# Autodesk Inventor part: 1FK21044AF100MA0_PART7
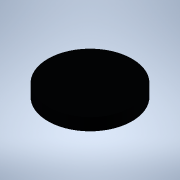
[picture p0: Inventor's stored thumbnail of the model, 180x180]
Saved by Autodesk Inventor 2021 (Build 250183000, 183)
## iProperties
Created: 2025-04
Part Number: 1FK21044AF100MA0_PART7
Material: Generic
Catalog Web Link: www.3dfindit.com
Description: -Servo synchronous motor
Document SubType Name: Modeling
Designer: psAdmin
Mass: 0.299142 g
Surface Area: 3.8585 cm^2
Volume: 0.299142 cm^3
Density: 1 g/cm^3
Appearance: PSOLRGB-38-46-56
Category: PARTsolutions
Title: 1FK21044AF100MA0_PART7
Author: Cadenas PARTsolutions
Comments: Servo synchronous motor
Sending System: PARTsolutions
Preprocessor: ST-DEVELOPER v19.3
PSOL_IDENT_0: {$CADENAS_DATA/23d-libs/siemens_ag/_cat_/ec/e4/1fk21044af100ma0.prj},213 {VTYP=3D},{NB=1FK21044AF100
PSOL_IDENT_1: MA0_PART7},{LINA=1FK21044AF100MA0_PART7},{NN=1FK21044AF100MA0_PART7},{NOPRJ=TRUE},{DATE=19.08.2025 1
PSOL_IDENT_2: 4:01:05},{GEOMDATE=30.07.2025 02:01:01},{VERSION=},{LINEID=10},{WBVAR=},{WBNUMERIC=}  {NB=1FK21044AF
PSOL_IDENT_3: 100MA0_PART7},{LINA=1FK21044AF100MA0_PART7},{KT=DUMMY},{PREVIEW=../../../_pool_/cb/72/p_d211_xx_0043
PSOL_IDENT_4: 4j.png},{DESCSHORT=SIMOTICS S-1FK2 HD, SINAMICS S210 3AC 400V-480V, 1.27 Nm, 3000 rpm},{DESCLONG=SIM
PSOL_IDENT_5: OTICS S-1FK2 HD servo motor M0=1.27 Nm; PN = 0.4 kW at nN=3000 rpm (380-480 V); PN = 0.2 kW at nN=15
PSOL_IDENT_6: 00 rpm (200-240 V); with holding brake; degree of protection IP64; cylindrical shaft D19x40mm; absol
PSOL_IDENT_7: ute encoder 22-bit + 12-bit multiturn (encoder AM22DQC); with OCC interface; plug size M17, rotatabl
PSOL_IDENT_8: e; SIMOTICS S-1FK2 servomotorfor a wide range of uses in industrial environments. SIMOTICS S‑1FK2 se
PSOL_IDENT_9: rvomotors are compact synchronous motors with a high dynamic performance that set themselves apart a
PSOL_IDENT_10: s a result of their high power density, degree of protection and overload capability. The motors are
PSOL_IDENT_11: available in two variants: as High Dynamic variant (highest dynamic performance as a result of the
PSOL_IDENT_12: low intrinsic moment of inertia for applications demanding a high dynamic performance with low moved
PSOL_IDENT_13: masses) - and as Compact variant (precise and stable closed-loop control for medium up to large mov
PSOL_IDENT_14: ed masses as a result of a medium intrinsic moment of inertia). SIMOTICSS‑1FK2 servomotors fully exp
PSOL_IDENT_15: loit their strengths in a system with the SINAMICSS210 frequency converter and simple connection usi
PSOL_IDENT_16: ng the one cable connection (OCC). Advantages include the short control and positioning times, fast
PSOL_IDENT_17: and precise correction of disturbing quantities as well as stable control with a high dynamic perfor
PSOL_IDENT_18: mance. The servo motors can be configured to address a wide range of requirements. For example with
PSOL_IDENT_19: and without holding brake, IP64 or IP65 degree of protection, singleturn or multiturn absolute encod
PSOL_IDENT_20: ers - to name just a few. Further, the servomotors are available in different shaft heights extendin
PSOL_IDENT_21: g from 20 to 100. A shaft sealing ring is available to achieve an IP65 degree of protection and for
PSOL_IDENT_22: subsequent mounting at the motor or as spare part. SIMOTICS - the optimum motor for each and every m
PSOL_IDENT_23: otion control application.},{INTNO=195125043275},{SUPPLIERALTNO=1FK2104-4AF10-0MA0},{MANUID=1FK21044
PSOL_IDENT_24: AF100MA0},{MANUNAME=Siemens},{MANUTYPEDESC=Synchronous motor 1FK2-HD 1.27 NM},{AAU732=SIMOTICS},{AAO
PSOL_IDENT_25: 057=S-1FK2},{AAU734=SIMOTICS S-1FK2 HD servo motor M0=1.27 Nm; PN = 0.4 kW at nN=3000 rpm (380-480 V
PSOL_IDENT_26: ); PN = 0.2 kW at nN=1500 rpm (200-240 V); with holding brake; degree of protection IP64; cylindrica
PSOL_IDENT_27: l shaft D19x40mm; absolute encoder 22-bit + 12-bit multiturn (encoder AM22DQC); with OCC interface;
PSOL_IDENT_28: plug size M17, rotatable;},{AAW338=Synchronous motor 1FK2-HD 1.27 NM},{AAO742=SIMOTICS},{AAO663=4042
PSOL_IDENT_29: 948694015},{NOCUPEROU=1},{PRICEQUANTITY=1},{QUANTITYMIN=1},{QUANTITYINT=1},{CTN=85015100},{COO=DE},{
PSOL_IDENT_30: AAO676=1FK2104-4AF10-0MA0},{AAO677=Siemens AG},{ORDERUNIT=C62},{CONTENTUNIT=C62}
NB: 1FK21044AF100MA0_PART7
NT: Servo synchronous motor
NBSYN: $MANUID._PART7
LINA: 1FK21044AF100MA0_PART7
CATALOG: SIEMENS
PREVIEW: ../../../_pool_/cb/72/p_d211_xx_00434j.png
DESCSHORT: SIMOTICS S-1FK2 HD, SINAMICS S210 3AC 400V-480V, 1.27 Nm, 3000 rpm
DESCLONG: SIMOTICS S-1FK2 HD servo motor M0=1.27 Nm; PN = 0.4 kW at nN=3000 rpm (380-480 V); PN = 0.2 kW at nN=1500 rpm (200-240 V); with holding brake; degree of protect
INTNO: 195125043275
SUPPLIERALTNO: 1FK2104-4AF10-0MA0
MANUID: 1FK21044AF100MA0
MANUNAME: Siemens
MANUTYPEDESC: Synchronous motor 1FK2-HD 1.27 NM
AAU732: SIMOTICS
AAO057: S-1FK2
AAU734: SIMOTICS S-1FK2 HD servo motor M0=1.27 Nm; PN = 0.4 kW at nN=3000 rpm (380-480 V); PN = 0.2 kW at nN=1500 rpm (200-240 V); with holding brake; degree of protect
AAW338: Synchronous motor 1FK2-HD 1.27 NM
AAO742: SIMOTICS
AAO663: 4042948694015.0
NOCUPEROU: 1
PRICEQUANTITY: 1
QUANTITYMIN: 1
QUANTITYINT: 1
CTN: 85015100
COO: DE
ARTICLENO: 1FK21044AF100MA0_PART7
BOMINFO: 1FK21044AF100MA0_PART7
CREATOR: CADENAS GmbH
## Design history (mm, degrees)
feature "2025_04_17_15_33_01_0642"
body "Solid1"
